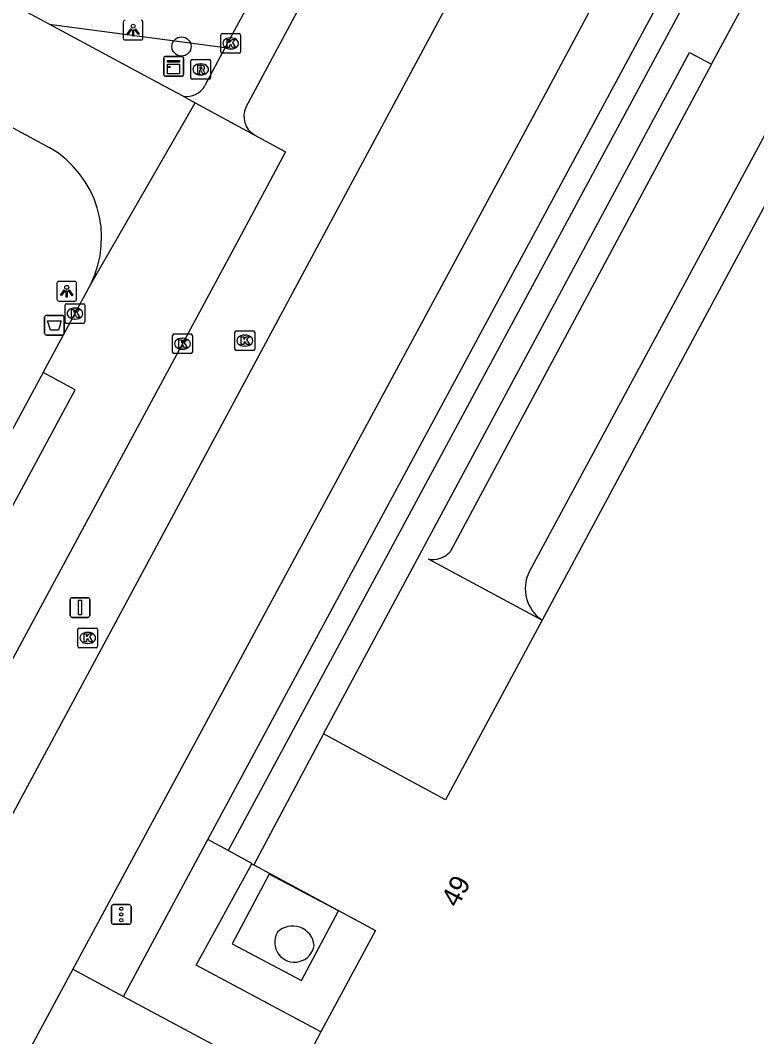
# Model space of a CAD drawing. Extents: x 159489 to 160304, y 383826 to 384530.
# Drawn here: x 159854.1 to 159891.4, y 384093.2 to 384144.8 of the extents above; entities that cross this region are included whole.
import ezdxf

# ---------------------------------------------------------------- set-up
doc = ezdxf.new("R2010")
doc.units = 0
for name, color, linetype in [('IMGEO_Afvalbak', 7, 'Continuous'), ('IMGEO_Boom', 7, 'Continuous'), ('IMGEO_Groenvoorziening', 7, 'Continuous'), ('IMGEO_Kast', 7, 'Continuous'), ('IMGEO_Kolk', 7, 'Continuous'), ('IMGEO_Lichtpunt', 7, 'Continuous'), ('IMGEO_Muur', 7, 'Continuous'), ('IMGEO_Opslagtank', 7, 'Continuous'), ('IMGEO_OVBaan_gesloten', 7, 'Continuous'), ('IMGEO_Pand', 7, 'Continuous'), ('IMGEO_Pand_nummerreeks', 7, 'Continuous'), ('IMGEO_Rijbaan_lokaal_gesloten', 7, 'Continuous'), ('IMGEO_Rioolput', 7, 'Continuous'), ('IMGEO_Verkeersbordpaal', 7, 'Continuous'), ('IMGEO_Verkeersregelinstallatiepaal', 7, 'Continuous'), ('IMGEO_Voetgangersgebied_gesloten', 7, 'Continuous'), ('IMGEO_Voetpad_open', 7, 'Continuous')]:
    doc.layers.add(name, color=color, linetype=linetype)

msp = doc.modelspace()

# ---------------------------------------------------------------- linework, layer by layer
at = {"layer": 'IMGEO_Afvalbak'}
for p, q in [((159855.311, 384128.9), (159855.311, 384129.7)), ((159855.311, 384129.7), (159855.311, 384128.9)), ((159855.411, 384129.8), (159856.201, 384129.8)), ((159856.201, 384129.8), (159855.411, 384129.8)), ((159856.301, 384129.7), (159856.301, 384128.9)), ((159856.301, 384128.9), (159856.301, 384129.7)), ((159856.201, 384128.8), (159855.411, 384128.8)), ((159855.411, 384128.8), (159856.201, 384128.8))]:
    msp.add_line(p, q, dxfattribs=at)
msp.add_lwpolyline([(159855.454, 384129.514), (159856.158, 384129.514), (159856.009, 384129.044), (159855.603, 384129.044), (159855.454, 384129.514)], dxfattribs=at)
for centre, start, end in [((159855.411, 384129.7), 90, 180), ((159855.411, 384129.7), 90, 180), ((159856.201, 384129.7), 0, 90), ((159856.201, 384129.7), 360, 90), ((159855.411, 384128.9), 180, 270), ((159855.411, 384128.9), 180, 270), ((159856.201, 384128.9), 270, 0), ((159856.201, 384128.9), 270, 0)]:
    msp.add_arc(centre, 0.1, start, end, dxfattribs=at)
at = {"layer": 'IMGEO_Boom'}
msp.add_circle((159862.255, 384143.433), 0.489, dxfattribs=at)
at = {"layer": 'IMGEO_Groenvoorziening'}
msp.add_lwpolyline([(159855.536, 384144.567), (159864.468, 384143.379)], dxfattribs=at)
at = {"layer": 'IMGEO_Kast'}
for p, q in [((159861.357, 384142.002), (159861.357, 384142.843)), ((159861.357, 384142.843), (159861.357, 384142.002)), ((159861.432, 384142.927), (159862.273, 384142.927)), ((159862.273, 384142.927), (159861.432, 384142.927)), ((159862.357, 384142.852), (159862.357, 384142.011)), ((159862.357, 384142.011), (159862.357, 384142.852)), ((159862.282, 384141.927), (159861.441, 384141.927)), ((159861.441, 384141.927), (159862.282, 384141.927))]:
    msp.add_line(p, q, dxfattribs=at)
for points in [[(159861.552, 384142.717), (159862.152, 384142.717), (159862.152, 384142.632), (159861.552, 384142.632), (159861.552, 384142.717)], [(159861.552, 384142.542), (159862.152, 384142.542), (159862.152, 384142.053), (159861.552, 384142.053), (159861.552, 384142.542)]]:
    msp.add_lwpolyline(points, dxfattribs=at)
msp.add_circle((159861.636, 384142.391), 0.0377, dxfattribs=at)
for centre, start, end in [((159861.435, 384142.849), 92.4484, 184.2845), ((159861.435, 384142.849), 92.4484, 184.2845), ((159862.279, 384142.849), 2.4484, 94.2845), ((159862.279, 384142.849), 2.4484, 94.2845), ((159861.435, 384142.005), 182.4484, 274.2845), ((159861.435, 384142.005), 182.4484, 274.2845), ((159862.279, 384142.005), 272.4484, 4.2845), ((159862.279, 384142.005), 272.4484, 4.2845)]:
    msp.add_arc(centre, 0.0779, start, end, dxfattribs=at)
at = {"layer": 'IMGEO_Kolk'}
for p, q in [((159864.251, 384143.163), (159864.251, 384144.015)), ((159864.326, 384144.089), (159865.178, 384144.089)), ((159864.739, 384143.869), (159864.764, 384143.869)), ((159865.252, 384144.015), (159865.252, 384143.163)), ((159864.762, 384143.309), (159864.737, 384143.309)), ((159865.178, 384143.089), (159864.326, 384143.089)), ((159856.424, 384130.391), (159857.276, 384130.391)), ((159856.349, 384129.465), (159856.349, 384130.317)), ((159856.837, 384130.171), (159856.862, 384130.171)), ((159857.35, 384130.317), (159857.35, 384129.465)), ((159857.276, 384129.391), (159856.424, 384129.391)), ((159856.86, 384129.611), (159856.835, 384129.611)), ((159861.881, 384128.858), (159862.733, 384128.858)), ((159864.967, 384128.092), (159864.967, 384128.944)), ((159865.042, 384129.018), (159865.894, 384129.018)), ((159865.968, 384128.944), (159865.968, 384128.092)), ((159861.806, 384127.932), (159861.806, 384128.784)), ((159862.294, 384128.638), (159862.319, 384128.638)), ((159862.807, 384128.784), (159862.807, 384127.932)), ((159865.455, 384128.798), (159865.48, 384128.798)), ((159862.733, 384127.858), (159861.881, 384127.858)), ((159862.317, 384128.078), (159862.292, 384128.078)), ((159865.894, 384128.018), (159865.042, 384128.018)), ((159865.478, 384128.238), (159865.453, 384128.238)), ((159857.074, 384113.943), (159857.926, 384113.943)), ((159856.999, 384113.017), (159856.999, 384113.869)), ((159857.487, 384113.723), (159857.512, 384113.723)), ((159858, 384113.869), (159858, 384113.017)), ((159857.926, 384112.943), (159857.074, 384112.943)), ((159857.51, 384113.163), (159857.485, 384113.163))]:
    msp.add_line(p, q, dxfattribs=at)
for points in [[(159864.251, 384143.163), (159864.251, 384144.015)], [(159864.326, 384144.089), (159865.178, 384144.089)], [(159864.572, 384143.789), (159864.695, 384143.789), (159864.695, 384143.638), (159864.825, 384143.789), (159864.989, 384143.789), (159864.843, 384143.638), (159864.996, 384143.389), (159864.844, 384143.389), (159864.759, 384143.553), (159864.695, 384143.486), (159864.695, 384143.389), (159864.572, 384143.389), (159864.572, 384143.789)], [(159865.252, 384144.015), (159865.252, 384143.163)], [(159865.178, 384143.089), (159864.326, 384143.089)], [(159856.424, 384130.391), (159857.276, 384130.391)], [(159856.349, 384129.465), (159856.349, 384130.317)], [(159856.67, 384130.091), (159856.793, 384130.091), (159856.793, 384129.94), (159856.923, 384130.091), (159857.087, 384130.091), (159856.941, 384129.94), (159857.094, 384129.691), (159856.942, 384129.691), (159856.857, 384129.855), (159856.793, 384129.788), (159856.793, 384129.691), (159856.67, 384129.691), (159856.67, 384130.091)], [(159857.35, 384130.317), (159857.35, 384129.465)], [(159857.276, 384129.391), (159856.424, 384129.391)], [(159861.881, 384128.858), (159862.733, 384128.858)], [(159864.967, 384128.092), (159864.967, 384128.944)], [(159865.042, 384129.018), (159865.894, 384129.018)], [(159865.968, 384128.944), (159865.968, 384128.092)], [(159861.806, 384127.932), (159861.806, 384128.784)], [(159862.127, 384128.558), (159862.25, 384128.558), (159862.25, 384128.407), (159862.38, 384128.558), (159862.544, 384128.558), (159862.398, 384128.407), (159862.551, 384128.158), (159862.399, 384128.158), (159862.314, 384128.322), (159862.25, 384128.255), (159862.25, 384128.158), (159862.127, 384128.158), (159862.127, 384128.558)], [(159862.807, 384128.784), (159862.807, 384127.932)], [(159865.288, 384128.718), (159865.411, 384128.718), (159865.411, 384128.567), (159865.541, 384128.718), (159865.705, 384128.718), (159865.559, 384128.567), (159865.712, 384128.318), (159865.56, 384128.318), (159865.475, 384128.482), (159865.411, 384128.415), (159865.411, 384128.318), (159865.288, 384128.318), (159865.288, 384128.718)], [(159862.733, 384127.858), (159861.881, 384127.858)], [(159865.894, 384128.018), (159865.042, 384128.018)], [(159857.074, 384113.943), (159857.926, 384113.943)], [(159856.999, 384113.017), (159856.999, 384113.869)], [(159857.32, 384113.643), (159857.443, 384113.643), (159857.443, 384113.492), (159857.573, 384113.643), (159857.737, 384113.643), (159857.591, 384113.492), (159857.744, 384113.243), (159857.592, 384113.243), (159857.507, 384113.407), (159857.443, 384113.34), (159857.443, 384113.243), (159857.32, 384113.243), (159857.32, 384113.643)], [(159858, 384113.869), (159858, 384113.017)], [(159857.926, 384112.943), (159857.074, 384112.943)]]:
    msp.add_lwpolyline(points, dxfattribs=at)
for centre, start, end in [((159864.328, 384144.013), 91.552, 178.448), ((159864.328, 384144.013), 91.552, 178.448), ((159865.176, 384144.013), 1.552, 88.448), ((159865.176, 384144.013), 1.552, 88.448), ((159864.328, 384143.165), 181.552, 268.448), ((159864.328, 384143.165), 181.552, 268.448), ((159865.176, 384143.165), 271.552, 358.448), ((159865.176, 384143.165), 271.552, 358.448), ((159856.426, 384130.315), 91.552, 178.448), ((159856.426, 384130.315), 91.552, 178.448), ((159857.274, 384130.315), 1.552, 88.448), ((159857.274, 384130.315), 1.552, 88.448), ((159856.426, 384129.467), 181.552, 268.448), ((159856.426, 384129.467), 181.552, 268.448), ((159857.274, 384129.467), 271.552, 358.448), ((159857.274, 384129.467), 271.552, 358.448), ((159861.883, 384128.782), 91.552, 178.448), ((159861.883, 384128.782), 91.552, 178.448), ((159862.731, 384128.782), 1.552, 88.448), ((159862.731, 384128.782), 1.552, 88.448), ((159865.044, 384128.942), 91.552, 178.448), ((159865.044, 384128.942), 91.552, 178.448), ((159865.892, 384128.942), 1.552, 88.448), ((159865.892, 384128.942), 1.552, 88.448), ((159861.883, 384127.934), 181.552, 268.448), ((159861.883, 384127.934), 181.552, 268.448), ((159862.731, 384127.934), 271.552, 358.448), ((159862.731, 384127.934), 271.552, 358.448), ((159865.044, 384128.094), 181.552, 268.448), ((159865.044, 384128.094), 181.552, 268.448), ((159865.892, 384128.094), 271.552, 358.448), ((159865.892, 384128.094), 271.552, 358.448), ((159857.076, 384113.867), 91.552, 178.448), ((159857.076, 384113.867), 91.552, 178.448), ((159857.924, 384113.867), 1.552, 88.448), ((159857.924, 384113.867), 1.552, 88.448), ((159857.076, 384113.019), 181.552, 268.448), ((159857.076, 384113.019), 181.552, 268.448), ((159857.924, 384113.019), 271.552, 358.448), ((159857.924, 384113.019), 271.552, 358.448)]:
    msp.add_arc(centre, 0.0765, start, end, dxfattribs=at)
for centre, major_axis, ratio, start_param, end_param in [((159864.738, 384143.589), (-0.387, 0.002), 0.722429, 4.712389, 7.853982), ((159864.763, 384143.589), (-0.39, 0.002), 0.717154, 1.570796, 4.712389), ((159856.836, 384129.891), (-0.387, 0.002), 0.722429, 4.712389, 7.853982), ((159856.861, 384129.891), (-0.39, 0.002), 0.717154, 1.570796, 4.712389), ((159862.293, 384128.358), (-0.387, 0.002), 0.722429, 4.712389, 7.853982), ((159862.318, 384128.358), (-0.39, 0.002), 0.717154, 1.570796, 4.712389), ((159865.454, 384128.518), (-0.387, 0.002), 0.722429, 4.712389, 7.853982), ((159865.479, 384128.518), (-0.39, 0.002), 0.717154, 1.570796, 4.712389), ((159857.486, 384113.443), (-0.387, 0.002), 0.722429, 4.712389, 7.853982), ((159857.511, 384113.443), (-0.39, 0.002), 0.717154, 1.570796, 4.712389)]:
    msp.add_ellipse(centre, major_axis=major_axis, ratio=ratio, start_param=start_param, end_param=end_param, dxfattribs=at)
at = {"layer": 'IMGEO_Lichtpunt'}
for p, q in [((159859.304, 384144.665), (159859.304, 384143.858)), ((159859.304, 384144.665), (159859.304, 384143.858)), ((159860.3, 384143.858), (159860.3, 384144.665)), ((159860.3, 384143.858), (159860.3, 384144.665)), ((159859.398, 384143.764), (159860.206, 384143.764)), ((159859.398, 384143.764), (159860.206, 384143.764)), ((159855.937, 384131.424), (159855.937, 384130.617)), ((159855.937, 384131.424), (159855.937, 384130.617)), ((159856.839, 384131.519), (159856.031, 384131.519)), ((159856.839, 384131.519), (159856.031, 384131.519)), ((159856.933, 384130.617), (159856.933, 384131.424)), ((159856.933, 384130.617), (159856.933, 384131.424)), ((159856.031, 384130.523), (159856.839, 384130.523)), ((159856.031, 384130.523), (159856.839, 384130.523))]:
    msp.add_line(p, q, dxfattribs=at)
for points in [[(159859.678, 384144.329), (159859.717, 384144.301), (159859.529, 384144.039), (159859.491, 384144.066), (159859.678, 384144.329)], [(159859.89, 384144.301), (159859.928, 384144.328), (159860.115, 384144.066), (159860.076, 384144.038), (159859.89, 384144.301)], [(159859.78, 384144.281), (159859.827, 384144.281), (159859.827, 384143.959), (159859.78, 384143.959), (159859.78, 384144.281)], [(159856.311, 384131.088), (159856.35, 384131.06), (159856.162, 384130.798), (159856.124, 384130.825), (159856.311, 384131.088)], [(159856.413, 384131.04), (159856.46, 384131.04), (159856.46, 384130.718), (159856.413, 384130.718), (159856.413, 384131.04)], [(159856.523, 384131.06), (159856.561, 384131.087), (159856.748, 384130.825), (159856.709, 384130.797), (159856.523, 384131.06)]]:
    msp.add_lwpolyline(points, dxfattribs=at)
for centre in [(159859.803, 384144.463), (159856.436, 384131.222)]:
    msp.add_circle(centre, 0.0994, dxfattribs=at)
for centre, start, end in [((159859.398, 384144.665), 90, 180), ((159859.398, 384144.665), 90, 180), ((159860.206, 384144.665), 0, 90), ((159860.206, 384144.665), 0, 90), ((159859.398, 384143.858), 180, 270), ((159859.398, 384143.858), 180, 270), ((159860.206, 384143.858), 270, 0), ((159860.206, 384143.858), 270, 360), ((159856.031, 384131.424), 90, 180), ((159856.031, 384131.424), 90, 180), ((159856.839, 384131.424), 0, 90), ((159856.839, 384131.424), 0, 90), ((159856.031, 384130.617), 180, 270), ((159856.031, 384130.617), 180, 270), ((159856.839, 384130.617), 270, 0), ((159856.839, 384130.617), 270, 360)]:
    msp.add_arc(centre, 0.0946, start, end, dxfattribs=at)
at = {"layer": 'IMGEO_Muur'}
msp.add_lwpolyline([(159869.459, 384108.58), (159888.023, 384143.133), (159889.137, 384142.535)], dxfattribs=at)
at = {"layer": 'IMGEO_Opslagtank'}
for centre, radius, start, end in [((159867.988, 384098.008), 1.007, 149.7426, 351.0081), ((159867.892, 384097.739), 1.097, 5.8577, 134.893)]:
    msp.add_arc(centre, radius, start, end, dxfattribs=at)
at = {"layer": 'IMGEO_OVBaan_gesloten'}
for points in [[(159851.185, 384099.877), (159859.407, 384115.156), (159875.621, 384145.351), (159877.35, 384148.57), (159879.235, 384152.071), (159881.839, 384156.886)], [(159887.537, 384153.695), (159884.987, 384148.942), (159883.06, 384145.447), (159880.834, 384141.273), (159856.746, 384096.64)], [(159856.746, 384096.64), (159854.136, 384091.803)]]:
    msp.add_lwpolyline(points, dxfattribs=at)
at = {"layer": 'IMGEO_Pand'}
for points in [[(159894.64, 384139.84), (159894.329, 384140), (159880.54, 384114.346)], [(159880.54, 384114.346), (159875.64, 384105.229), (159869.459, 384108.58)], [(159869.459, 384108.58), (159865.92, 384101.929)], [(159865.92, 384101.929), (159872.089, 384098.599), (159869.328, 384093.464)], [(159869.328, 384093.464), (159868.739, 384092.369)]]:
    msp.add_lwpolyline(points, dxfattribs=at)
at = {"layer": 'IMGEO_Rijbaan_lokaal_gesloten'}
for points in [[(159855.536, 384144.567), (159759.321, 384196.257)], [(159889.137, 384142.535), (159892.986, 384149.68)], [(159862.337, 384140.91), (159861.705, 384141.252), (159855.536, 384144.567)], [(159894.462, 384143.834), (159893.227, 384141.526), (159879.882, 384116.79)], [(159869.459, 384108.58), (159888.023, 384143.133), (159889.137, 384142.535)], [(159889.137, 384142.535), (159875.881, 384117.815)], [(159850.655, 384140.94), (159855.579, 384138.299)], [(159862.337, 384140.91), (159862.941, 384140.583)], [(159857.656, 384131.382), (159862.941, 384140.583)], [(159862.941, 384140.583), (159865.935, 384138.962)], [(159865.935, 384138.962), (159867.537, 384138.085), (159865.274, 384133.885), (159850.273, 384106.058)], [(159855.234, 384126.903), (159857.656, 384131.382)], [(159847.394, 384112.379), (159849.025, 384111.514), (159849.669, 384112.727), (159856.858, 384126.025), (159855.234, 384126.903)], [(159874.761, 384117.45), (159880.54, 384114.346)], [(159856.746, 384096.64), (159859.316, 384095.263)], [(159859.316, 384095.263), (159900.235, 384073.345), (159902.185, 384072.3)]]:
    msp.add_lwpolyline(points, dxfattribs=at)
for centre, radius, start, end in [((159852.913, 384133.728), 5.291, 333.6798, 59.7476), ((159875.015, 384118.571), 1.149, 257.2224, 318.8784), ((159881.625, 384115.949), 1.935, 154.2342, 235.9028)]:
    msp.add_arc(centre, radius, start, end, dxfattribs=at)
at = {"layer": 'IMGEO_Rioolput'}
for p, q in [((159862.804, 384142.772), (159863.656, 384142.772)), ((159862.729, 384141.846), (159862.729, 384142.698)), ((159863.217, 384142.552), (159863.242, 384142.552)), ((159863.73, 384142.698), (159863.73, 384141.846)), ((159863.656, 384141.772), (159862.804, 384141.772)), ((159863.24, 384141.992), (159863.215, 384141.992))]:
    msp.add_line(p, q, dxfattribs=at)
for points in [[(159862.804, 384142.772), (159863.656, 384142.772)], [(159862.729, 384141.846), (159862.729, 384142.698)], [(159863.318, 384142.47), (159863.066, 384142.472), (159863.066, 384142.072)], [(159863.244, 384142.391), (159863.19, 384142.391), (159863.19, 384142.31)], [(159863.19, 384142.31), (159863.242, 384142.31)], [(159863.73, 384142.698), (159863.73, 384141.846)], [(159863.656, 384141.772), (159862.804, 384141.772)], [(159863.066, 384142.072), (159863.19, 384142.072), (159863.19, 384142.234), (159863.201, 384142.234)], [(159863.248, 384142.205), (159863.319, 384142.072), (159863.459, 384142.072), (159863.394, 384142.198)]]:
    msp.add_lwpolyline(points, dxfattribs=at)
for centre, radius, start, end in [((159862.806, 384142.696), 0.0765, 91.552, 178.448), ((159862.806, 384142.696), 0.0765, 91.552, 178.448), ((159863.654, 384142.696), 0.0765, 1.552, 88.448), ((159863.654, 384142.696), 0.0765, 1.552, 88.448), ((159863.226, 384142.499), 0.19, 274.7715, 282.9687), ((159863.25, 384142.295), 0.0964, 77.0061, 93.1865), ((159863.264, 384142.352), 0.0378, 276.6634, 79.6772), ((159863.317, 384142.36), 0.109, 350.3612, 89.416), ((159863.315, 384142.36), 0.112, 277.5842, 350.9817), ((159863.299, 384142.145), 0.108, 29.5134, 73.7905), ((159862.806, 384141.848), 0.0765, 181.552, 268.448), ((159862.806, 384141.848), 0.0765, 181.552, 268.448), ((159863.2, 384142.181), 0.0533, 26.0293, 88.6989), ((159863.654, 384141.848), 0.0765, 271.552, 358.448), ((159863.654, 384141.848), 0.0765, 271.552, 358.448)]:
    msp.add_arc(centre, radius, start, end, dxfattribs=at)
for centre, major_axis, ratio, start_param, end_param in [((159863.216, 384142.272), (-0.387, 0.002), 0.722429, 4.712389, 7.853982), ((159863.241, 384142.272), (-0.39, 0.002), 0.717154, 1.570796, 4.712389)]:
    msp.add_ellipse(centre, major_axis=major_axis, ratio=ratio, start_param=start_param, end_param=end_param, dxfattribs=at)
at = {"layer": 'IMGEO_Verkeersbordpaal'}
for p, q in [((159856.714, 384115.483), (159857.504, 384115.483)), ((159857.504, 384115.483), (159856.714, 384115.483)), ((159856.614, 384114.583), (159856.614, 384115.383)), ((159856.614, 384115.383), (159856.614, 384114.583)), ((159857.604, 384115.383), (159857.604, 384114.583)), ((159857.604, 384114.583), (159857.604, 384115.383)), ((159857.504, 384114.483), (159856.714, 384114.483)), ((159856.714, 384114.483), (159857.504, 384114.483))]:
    msp.add_line(p, q, dxfattribs=at)
msp.add_lwpolyline([(159857.034, 384115.358), (159857.184, 384115.358), (159857.184, 384114.608), (159857.034, 384114.608), (159857.034, 384115.358)], dxfattribs=at)
for centre, start, end in [((159856.714, 384115.383), 90, 180), ((159856.714, 384115.383), 90, 180), ((159857.504, 384115.383), 0, 90), ((159857.504, 384115.383), 360, 90), ((159856.714, 384114.583), 180, 270), ((159856.714, 384114.583), 180, 270), ((159857.504, 384114.583), 270, 0), ((159857.504, 384114.583), 270, 0)]:
    msp.add_arc(centre, 0.1, start, end, dxfattribs=at)
at = {"layer": 'IMGEO_Verkeersregelinstallatiepaal'}
for p, q in [((159858.705, 384099.021), (159858.705, 384099.821)), ((159858.705, 384099.821), (159858.705, 384099.021)), ((159858.805, 384099.921), (159859.595, 384099.921)), ((159859.595, 384099.921), (159858.805, 384099.921)), ((159859.695, 384099.821), (159859.695, 384099.021)), ((159859.695, 384099.021), (159859.695, 384099.821)), ((159859.595, 384098.921), (159858.805, 384098.921)), ((159858.805, 384098.921), (159859.595, 384098.921))]:
    msp.add_line(p, q, dxfattribs=at)
for centre in [(159859.2, 384099.711), (159859.2, 384099.421), (159859.2, 384099.131)]:
    msp.add_circle(centre, 0.085, dxfattribs=at)
for centre, start, end in [((159858.805, 384099.821), 90, 180), ((159858.805, 384099.821), 90, 180), ((159859.595, 384099.821), 0, 90), ((159859.595, 384099.821), 360, 90), ((159858.805, 384099.021), 180, 270), ((159858.805, 384099.021), 180, 270), ((159859.595, 384099.021), 270, 0), ((159859.595, 384099.021), 270, 0)]:
    msp.add_arc(centre, 0.1, start, end, dxfattribs=at)
at = {"layer": 'IMGEO_Voetgangersgebied_gesloten'}
for points in [[(159873.563, 384160.232), (159864.468, 384143.379)], [(159865.52, 384140.339), (159875.579, 384159.098)], [(159864.468, 384143.379), (159863.439, 384141.451)]]:
    msp.add_lwpolyline(points, dxfattribs=at)
for centre, radius, start, end in [((159862.502, 384141.966), 1.069, 261.1101, 331.1851), ((159866.5, 384139.883), 1.08, 155.0483, 238.4952)]:
    msp.add_arc(centre, radius, start, end, dxfattribs=at)
at = {"layer": 'IMGEO_Voetpad_open'}
for points in [[(159863.593, 384103.225), (159890.072, 384152.355)], [(159891.089, 384151.818), (159864.623, 384102.661)], [(159855.234, 384126.903), (159848.041, 384113.599), (159847.394, 384112.379)], [(159859.316, 384095.263), (159863.593, 384103.225)], [(159864.623, 384102.661), (159863.593, 384103.225)], [(159865.816, 384101.986), (159865.829, 384102.01), (159864.623, 384102.661)], [(159869.328, 384093.464), (159862.995, 384096.849), (159865.816, 384101.986)], [(159865.816, 384101.986), (159865.92, 384101.929)], [(159866.693, 384101.466), (159864.823, 384097.928), (159868.341, 384096.068), (159870.211, 384099.607), (159866.693, 384101.466)]]:
    msp.add_lwpolyline(points, dxfattribs=at)

# ---------------------------------------------------------------- texts
at = {"layer": 'IMGEO_Pand_nummerreeks'}
msp.add_text('49', height=1, rotation=62.0628, dxfattribs=at).set_placement((159876.254, 384099.721))

doc.saveas('drawing.dxf')
